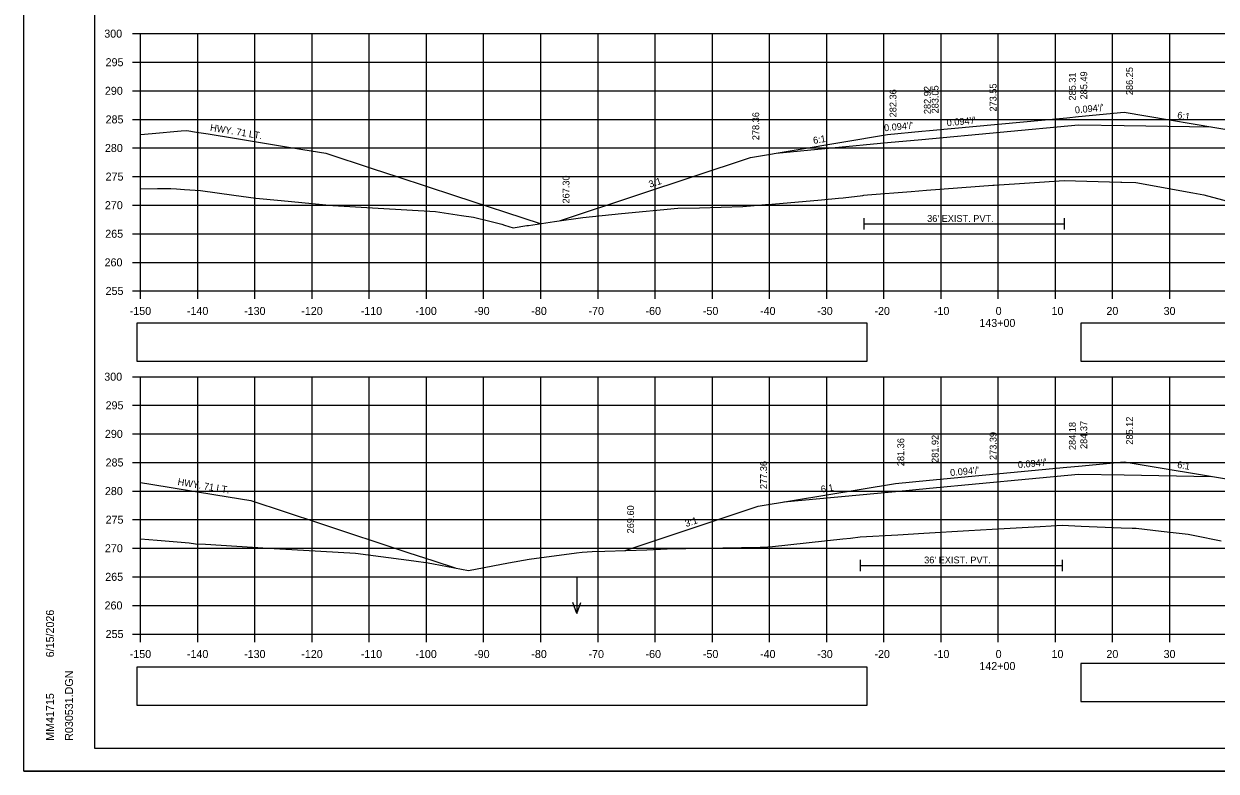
# Model space of a CAD drawing. Extents: x 285 to 4233, y -659 to 3710.
# Drawn here: x 2389.1 to 2597.6, y 2749.6 to 2880.3 of the extents above; entities that cross this region are included whole.
import ezdxf

# ---------------------------------------------------------------- set-up
doc = ezdxf.new("R2010")
doc.units = 0
for name, color, linetype in [('R_Alt Surface', 7, 'Continuous'), ('R_Axis', 7, 'Continuous'), ('R_Axis Annot', 7, 'Continuous'), ('R_Border', 7, 'Continuous'), ('R_Exist Surface', 7, 'Continuous'), ('R_Fin Surface', 7, 'Continuous'), ('R_Grid', 7, 'Continuous'), ('R_No Plot', 7, 'Continuous'), ('R_Water', 7, 'Continuous'), ('R_Water Annot', 7, 'Continuous'), ('R_Xsect Elev', 7, 'Continuous'), ('R_Xsect Slope', 7, 'Continuous')]:
    doc.layers.add(name, color=color, linetype=linetype)

msp = doc.modelspace()

# ---------------------------------------------------------------- linework, layer by layer
at = {"layer": 'R_Alt Surface'}
for points in [[(2520.64, 2857.66), (2540.14, 2859.49), (2546.14, 2860.05), (2546.14, 2860.05), (2573.5, 2862.62), (2581.5, 2862.5), (2596.74, 2862.25)], [(2520.64, 2857.66), (2540.14, 2859.49), (2546.14, 2860.05), (2546.14, 2860.05), (2573.5, 2862.62), (2581.5, 2862.5), (2596.74, 2862.25)], [(2520.64, 2857.66), (2540.14, 2859.49), (2546.14, 2860.05), (2546.14, 2860.05), (2573.5, 2862.62), (2581.5, 2862.5), (2596.74, 2862.25)], [(2535.99, 2846.29), (2535.99, 2844.29)], [(2571.03, 2846.29), (2571.03, 2844.29)], [(2535.99, 2845.29), (2571.03, 2845.29)], [(2522.01, 2796.65), (2541.5, 2798.49), (2547.5, 2799.05), (2547.5, 2799.05), (2573.5, 2801.49), (2581.5, 2801.37), (2596.74, 2801.12)], [(2522.01, 2796.65), (2541.5, 2798.49), (2547.5, 2799.05), (2547.5, 2799.05), (2573.5, 2801.49), (2581.5, 2801.37), (2596.74, 2801.12)], [(2522.01, 2796.65), (2541.5, 2798.49), (2547.5, 2799.05), (2547.5, 2799.05), (2573.5, 2801.49), (2581.5, 2801.37), (2596.74, 2801.12)], [(2535.35, 2786.52), (2535.35, 2784.52)], [(2570.7, 2786.52), (2570.7, 2784.52)], [(2535.35, 2785.52), (2570.7, 2785.52)]]:
    msp.add_lwpolyline(points, dxfattribs=at)
at = {"layer": 'R_Axis'}
for p, q in [((2408.1, 2878.55), (2409.5, 2878.55)), ((2409.5, 2833.55), (2409.5, 2878.55)), ((2408.1, 2873.55), (2409.5, 2873.55)), ((2408.1, 2868.55), (2409.5, 2868.55)), ((2408.1, 2863.55), (2409.5, 2863.55)), ((2408.1, 2858.55), (2409.5, 2858.55)), ((2408.1, 2853.55), (2409.5, 2853.55)), ((2408.1, 2848.55), (2409.5, 2848.55)), ((2408.1, 2843.55), (2409.5, 2843.55)), ((2408.1, 2838.55), (2409.5, 2838.55)), ((2408.1, 2833.55), (2409.5, 2833.55)), ((2409.5, 2833.55), (2709.5, 2833.55)), ((2409.5, 2832.15), (2409.5, 2833.55)), ((2419.5, 2832.15), (2419.5, 2833.55)), ((2429.5, 2832.15), (2429.5, 2833.55)), ((2439.5, 2832.15), (2439.5, 2833.55)), ((2449.5, 2832.15), (2449.5, 2833.55)), ((2459.5, 2832.15), (2459.5, 2833.55)), ((2469.5, 2832.15), (2469.5, 2833.55)), ((2479.5, 2832.15), (2479.5, 2833.55)), ((2489.5, 2832.15), (2489.5, 2833.55)), ((2499.5, 2832.15), (2499.5, 2833.55)), ((2509.5, 2832.15), (2509.5, 2833.55)), ((2519.5, 2832.15), (2519.5, 2833.55)), ((2529.5, 2832.15), (2529.5, 2833.55)), ((2539.5, 2832.15), (2539.5, 2833.55)), ((2549.5, 2832.15), (2549.5, 2833.55)), ((2559.5, 2832.15), (2559.5, 2833.55)), ((2569.5, 2832.15), (2569.5, 2833.55)), ((2579.5, 2832.15), (2579.5, 2833.55)), ((2589.5, 2832.15), (2589.5, 2833.55)), ((2408.1, 2818.55), (2409.5, 2818.55)), ((2409.5, 2773.55), (2409.5, 2818.55)), ((2408.1, 2813.55), (2409.5, 2813.55)), ((2408.1, 2808.55), (2409.5, 2808.55)), ((2408.1, 2803.55), (2409.5, 2803.55)), ((2408.1, 2798.55), (2409.5, 2798.55)), ((2408.1, 2793.55), (2409.5, 2793.55)), ((2408.1, 2788.55), (2409.5, 2788.55)), ((2408.1, 2783.55), (2409.5, 2783.55)), ((2408.1, 2778.55), (2409.5, 2778.55)), ((2408.1, 2773.55), (2409.5, 2773.55)), ((2409.5, 2773.55), (2709.5, 2773.55)), ((2409.5, 2772.15), (2409.5, 2773.55)), ((2419.5, 2772.15), (2419.5, 2773.55)), ((2429.5, 2772.15), (2429.5, 2773.55)), ((2439.5, 2772.15), (2439.5, 2773.55)), ((2449.5, 2772.15), (2449.5, 2773.55)), ((2459.5, 2772.15), (2459.5, 2773.55)), ((2469.5, 2772.15), (2469.5, 2773.55)), ((2479.5, 2772.15), (2479.5, 2773.55)), ((2489.5, 2772.15), (2489.5, 2773.55)), ((2499.5, 2772.15), (2499.5, 2773.55)), ((2509.5, 2772.15), (2509.5, 2773.55)), ((2519.5, 2772.15), (2519.5, 2773.55)), ((2529.5, 2772.15), (2529.5, 2773.55)), ((2539.5, 2772.15), (2539.5, 2773.55)), ((2549.5, 2772.15), (2549.5, 2773.55)), ((2559.5, 2772.15), (2559.5, 2773.55)), ((2569.5, 2772.15), (2569.5, 2773.55)), ((2579.5, 2772.15), (2579.5, 2773.55)), ((2589.5, 2772.15), (2589.5, 2773.55))]:
    msp.add_line(p, q, dxfattribs=at)
at = {"layer": 'R_Axis Annot'}
for points in [[(2408.87, 2821.27), (2536.56, 2821.27), (2536.56, 2827.93), (2408.87, 2827.93)], [(2573.96, 2821.27), (2714.32, 2821.27), (2714.32, 2827.92), (2573.96, 2827.92)], [(2408.87, 2761.12), (2536.56, 2761.12), (2536.56, 2767.77), (2408.87, 2767.77)], [(2573.96, 2761.72), (2714.32, 2761.72), (2714.32, 2768.37), (2573.96, 2768.37)]]:
    msp.add_lwpolyline(points, close=True, dxfattribs=at)
at = {"layer": 'R_Border'}
for p, q in [((2401.5, 2753.55), (2401.5, 2959.01)), ((2401.5, 2753.55), (2401.5, 2753.55)), ((2717.68, 2753.55), (2401.5, 2753.55))]:
    msp.add_line(p, q, dxfattribs=at)
at = {"layer": 'R_Exist Surface'}
for points in [[(2409.5, 2851.4), (2412.44, 2851.48), (2414.82, 2851.44), (2415.76, 2851.42), (2417.16, 2851.3), (2419.96, 2851.12), (2419.97, 2851.11), (2425.81, 2850.31), (2429.64, 2849.75), (2429.66, 2849.75), (2434.12, 2849.35), (2443.15, 2848.47), (2451.04, 2848.04), (2461.08, 2847.47), (2465.62, 2846.76), (2467.73, 2846.43), (2470.57, 2845.75), (2472.7, 2845.25), (2473.15, 2845.06), (2474.65, 2844.57), (2477.05, 2844.97), (2477.35, 2845.02), (2481.9, 2845.69), (2486.85, 2846.4), (2493.61, 2847.11), (2503.46, 2848.04), (2507.25, 2848.07), (2514.83, 2848.31), (2518.81, 2848.65), (2519.91, 2848.73), (2528.58, 2849.49), (2531.53, 2849.75), (2532.35, 2849.82), (2535.84, 2850.27), (2535.99, 2850.29), (2536.64, 2850.34), (2544.28, 2850.96), (2546.93, 2851.18), (2558.54, 2852.03), (2558.8, 2852.05), (2564.95, 2852.46), (2571.03, 2852.87), (2580.94, 2852.56), (2581.08, 2852.56), (2581.12, 2852.56), (2583.56, 2852.5), (2593.52, 2850.71), (2595.46, 2850.36), (2606.11, 2847.51)], [(2409.5, 2790.18), (2412.4, 2789.94), (2418.02, 2789.47), (2419.09, 2789.35), (2420.87, 2789.26), (2431.83, 2788.56), (2437.97, 2788.23), (2447.1, 2787.71), (2457.3, 2786.33), (2459.78, 2786), (2460.76, 2785.81), (2466.84, 2784.67), (2473.83, 2785.98), (2477.45, 2786.62), (2485.75, 2787.72), (2486.75, 2787.87), (2488.48, 2787.96), (2490.71, 2788.02), (2498.06, 2788.29), (2501.62, 2788.42), (2517.86, 2788.75), (2519.22, 2788.77), (2520.02, 2788.86), (2532.31, 2790.2), (2533.66, 2790.34), (2535.35, 2790.52), (2541.96, 2790.9), (2546.48, 2791.16), (2554.37, 2791.63), (2558.44, 2791.88), (2566.83, 2792.34), (2570.7, 2792.56), (2574.01, 2792.41), (2581.01, 2792.1), (2582.89, 2792.05), (2583.61, 2792.04), (2588.01, 2791.52), (2592.73, 2791.01), (2593.88, 2790.76), (2598.45, 2789.83)]]:
    msp.add_lwpolyline(points, dxfattribs=at)
at = {"layer": 'R_Fin Surface'}
for points in [[(2482.96, 2845.84), (2496.27, 2850.28), (2516.14, 2856.91), (2540.14, 2860.91), (2546.14, 2861.47), (2547.5, 2861.6), (2571.5, 2863.85), (2573.5, 2864.04), (2581.5, 2864.79), (2601.5, 2861.46), (2647, 2846.29), (2649.75, 2847.21)], [(2409.5, 2860.93), (2411.52, 2861.1), (2416.62, 2861.53), (2417.6, 2861.61), (2419.26, 2861.34), (2421.32, 2861.01), (2425.94, 2860.25), (2434.7, 2858.82), (2437.87, 2858.29), (2441.9, 2857.64), (2450.03, 2854.96), (2454.5, 2853.5), (2464.41, 2850.24), (2479.37, 2845.32)], [(2494.24, 2788.15), (2517.5, 2795.9), (2541.5, 2799.9), (2547.5, 2800.47), (2571.5, 2802.72), (2573.5, 2802.91), (2581.5, 2803.66), (2601.5, 2800.33), (2644.62, 2785.96), (2653.73, 2788.99)], [(2409.5, 2800.07), (2411.3, 2799.77), (2422.68, 2797.9), (2428.8, 2796.89), (2440.79, 2792.93), (2456.25, 2787.83), (2460.8, 2786.33), (2464.5, 2785.11)]]:
    msp.add_lwpolyline(points, dxfattribs=at)
at = {"layer": 'R_Grid'}
for p, q in [((2409.5, 2878.55), (2709.5, 2878.55)), ((2409.5, 2833.55), (2409.5, 2878.55)), ((2419.5, 2833.55), (2419.5, 2878.55)), ((2429.5, 2833.55), (2429.5, 2878.55)), ((2439.5, 2833.55), (2439.5, 2878.55)), ((2449.5, 2833.55), (2449.5, 2878.55)), ((2459.5, 2833.55), (2459.5, 2878.55)), ((2469.5, 2833.55), (2469.5, 2878.55)), ((2479.5, 2833.55), (2479.5, 2878.55)), ((2489.5, 2833.55), (2489.5, 2878.55)), ((2499.5, 2833.55), (2499.5, 2878.55)), ((2509.5, 2833.55), (2509.5, 2878.55)), ((2519.5, 2833.55), (2519.5, 2878.55)), ((2529.5, 2833.55), (2529.5, 2878.55)), ((2539.5, 2833.55), (2539.5, 2878.55)), ((2549.5, 2833.55), (2549.5, 2878.55)), ((2559.5, 2833.55), (2559.5, 2878.55)), ((2569.5, 2833.55), (2569.5, 2878.55)), ((2579.5, 2833.55), (2579.5, 2878.55)), ((2589.5, 2833.55), (2589.5, 2878.55)), ((2409.5, 2873.55), (2709.5, 2873.55)), ((2409.5, 2868.55), (2709.5, 2868.55)), ((2409.5, 2863.55), (2709.5, 2863.55)), ((2409.5, 2858.55), (2709.5, 2858.55)), ((2409.5, 2853.55), (2709.5, 2853.55)), ((2409.5, 2848.55), (2709.5, 2848.55)), ((2409.5, 2843.55), (2709.5, 2843.55)), ((2409.5, 2838.55), (2709.5, 2838.55)), ((2409.5, 2833.55), (2709.5, 2833.55)), ((2409.5, 2818.55), (2709.5, 2818.55)), ((2409.5, 2773.55), (2409.5, 2818.55)), ((2419.5, 2773.55), (2419.5, 2818.55)), ((2429.5, 2773.55), (2429.5, 2818.55)), ((2439.5, 2773.55), (2439.5, 2818.55)), ((2449.5, 2773.55), (2449.5, 2818.55)), ((2459.5, 2773.55), (2459.5, 2818.55)), ((2469.5, 2773.55), (2469.5, 2818.55)), ((2479.5, 2773.55), (2479.5, 2818.55)), ((2489.5, 2773.55), (2489.5, 2818.55)), ((2499.5, 2773.55), (2499.5, 2818.55)), ((2509.5, 2773.55), (2509.5, 2818.55)), ((2519.5, 2773.55), (2519.5, 2818.55)), ((2529.5, 2773.55), (2529.5, 2818.55)), ((2539.5, 2773.55), (2539.5, 2818.55)), ((2549.5, 2773.55), (2549.5, 2818.55)), ((2559.5, 2773.55), (2559.5, 2818.55)), ((2569.5, 2773.55), (2569.5, 2818.55)), ((2579.5, 2773.55), (2579.5, 2818.55)), ((2589.5, 2773.55), (2589.5, 2818.55)), ((2409.5, 2813.55), (2709.5, 2813.55)), ((2409.5, 2808.55), (2709.5, 2808.55)), ((2409.5, 2803.55), (2709.5, 2803.55)), ((2409.5, 2798.55), (2709.5, 2798.55)), ((2409.5, 2793.55), (2709.5, 2793.55)), ((2409.5, 2788.55), (2709.5, 2788.55)), ((2409.5, 2783.55), (2709.5, 2783.55)), ((2409.5, 2778.55), (2709.5, 2778.55)), ((2409.5, 2773.55), (2709.5, 2773.55))]:
    msp.add_line(p, q, dxfattribs=at)
at = {"layer": 'R_No Plot'}
msp.add_line((2389.1, 2749.57), (2722.43, 2749.57), dxfattribs=at)
for points in [[(2389.09, 2962.9), (2722.43, 2962.9), (2722.43, 2749.56), (2389.09, 2749.56)], [(2635.42, 2959.01), (2655.04, 2959.01), (2655.04, 2949.13), (2671.15, 2949.13), (2694.35, 2949.13), (2694.47, 2920.97), (2717.68, 2920.97), (2717.68, 2753.55), (2401.5, 2753.55), (2401.5, 2959.01)]]:
    msp.add_lwpolyline(points, close=True, dxfattribs=at)
at = {"layer": 'R_Water Annot'}
for p, q in [((2485.81, 2783.45), (2485.81, 2777.16)), ((2485.81, 2777.16), (2485.11, 2779.09)), ((2485.81, 2777.16), (2486.51, 2779.09))]:
    msp.add_line(p, q, dxfattribs=at)
at = {"layer": 'R_Xsect Elev'}
for p, q in [((2559.5, 2852.1), (2559.5, 2870.78)), ((2559.5, 2791.94), (2559.5, 2810))]:
    msp.add_line(p, q, dxfattribs=at)

# ---------------------------------------------------------------- texts
at = {"layer": 'R_Axis Annot'}
for s, p in [('300', (2403.16, 2877.85)), ('295', (2403.39, 2872.85)), ('290', (2403.27, 2867.85)), ('285', (2403.39, 2862.85)), ('280', (2403.27, 2857.85)), ('275', (2403.39, 2852.85)), ('270', (2403.27, 2847.85)), ('265', (2403.33, 2842.85)), ('260', (2403.21, 2837.85)), ('255', (2403.39, 2832.85)), ('-150', (2407.61, 2829.35)), ('-140', (2417.61, 2829.35)), ('-130', (2427.61, 2829.35)), ('-120', (2437.61, 2829.35)), ('-110', (2448.01, 2829.35)), ('-100', (2457.56, 2829.35)), ('-90', (2467.84, 2829.35)), ('-80', (2477.84, 2829.35)), ('-70', (2487.84, 2829.35)), ('-60', (2497.81, 2829.35)), ('-50', (2507.84, 2829.35)), ('-40', (2517.84, 2829.35)), ('-30', (2527.84, 2829.35)), ('-20', (2537.84, 2829.35)), ('-10', (2548.24, 2829.35)), ('0', (2559.04, 2829.35)), ('10', (2568.81, 2829.35)), ('20', (2578.41, 2829.35)), ('30', (2588.41, 2829.35)), ('143+00', (2556.19, 2827.25)), ('300', (2403.16, 2817.85)), ('295', (2403.39, 2812.85)), ('290', (2403.27, 2807.85)), ('285', (2403.39, 2802.85)), ('280', (2403.27, 2797.85)), ('275', (2403.39, 2792.85)), ('270', (2403.27, 2787.85)), ('265', (2403.33, 2782.85)), ('260', (2403.21, 2777.85)), ('255', (2403.39, 2772.85)), ('-150', (2407.61, 2769.35)), ('-140', (2417.61, 2769.35)), ('-130', (2427.61, 2769.35)), ('-120', (2437.61, 2769.35)), ('-110', (2448.01, 2769.35)), ('-100', (2457.56, 2769.35)), ('-90', (2467.84, 2769.35)), ('-80', (2477.84, 2769.35)), ('-70', (2487.84, 2769.35)), ('-60', (2497.81, 2769.35)), ('-50', (2507.84, 2769.35)), ('-40', (2517.84, 2769.35)), ('-30', (2527.84, 2769.35)), ('-20', (2537.84, 2769.35)), ('-10', (2548.24, 2769.35)), ('0', (2559.04, 2769.35)), ('10', (2568.81, 2769.35)), ('20', (2578.41, 2769.35)), ('30', (2588.41, 2769.35)), ('142+00', (2556.19, 2767.25))]:
    msp.add_text(s, height=1.4, dxfattribs=at).set_placement(p)
at = {"layer": 'R_Border'}
for s, p in [('6/15/2026', (2394.37, 2769.47)), ('R030531.DGN', (2397.69, 2754.87)), ('MM41715', (2394.37, 2754.87))]:
    msp.add_text(s, height=1.4, rotation=90, dxfattribs=at).set_placement(p)
at = {"layer": 'R_Water'}
for rotation, p in [(350.7002, (2421.6, 2861.57)), (350.6571, (2415.92, 2799.62))]:
    msp.add_text('HWY. 71 LT.', height=1.2, rotation=rotation, dxfattribs=at).set_placement(p)
for p in [(2547.06, 2845.62), (2546.54, 2785.9)]:
    msp.add_text("36' EXIST. PVT.", height=1.2, dxfattribs=at).set_placement(p)
at = {"layer": 'R_Xsect Elev'}
for s, p in [('285.31', (2573.05, 2866.85)), ('285.49', (2575.05, 2867.04)), ('286.25', (2583.05, 2867.79)), ('282.92', (2547.69, 2864.47)), ('283.05', (2549.05, 2864.6)), ('273.55', (2559.2, 2864.92)), ('282.36', (2541.69, 2863.91)), ('278.36', (2517.69, 2859.91)), ('267.30', (2484.51, 2848.84)), ('284.37', (2575.05, 2805.91)), ('285.12', (2583.05, 2806.66)), ('273.39', (2559.2, 2803.98)), ('284.18', (2573.05, 2805.72)), ('281.36', (2543.05, 2802.9)), ('281.92', (2549.05, 2803.47)), ('277.36', (2519.05, 2798.9)), ('269.60', (2495.79, 2791.15))]:
    msp.add_text(s, height=1.2, rotation=90, dxfattribs=at).set_placement(p)
at = {"layer": 'R_Xsect Slope'}
for s, rotation, p in [("0.094'/'", 5.37, (2572.95, 2864.59)), ('6:1', 350.5377, (2590.73, 2863.76)), ("0.094'/'", 5.37, (2539.58, 2861.46)), ("0.094'/'", 5.37, (2550.53, 2862.36)), ('6:1', 9.4623, (2527.21, 2859.26)), ('3:1', 18.4349, (2498.6, 2851.59)), ("0.094'/'", 5.37, (2551.13, 2801.17)), ("0.094'/'", 5.37, (2562.98, 2802.55)), ('6:1', 350.5377, (2590.73, 2802.63)), ('6:1', 9.4623, (2528.57, 2798.26)), ('3:1', 18.4349, (2504.92, 2792.24))]:
    msp.add_text(s, height=1.2, rotation=rotation, dxfattribs=at).set_placement(p)

doc.saveas('drawing.dxf')
